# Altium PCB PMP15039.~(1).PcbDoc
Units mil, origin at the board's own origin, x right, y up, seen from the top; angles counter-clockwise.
Board outline 370 x 722 mil, 4 copper layers (Top Layer, MidLayer1, MidLayer2, Bottom Layer), stack 59.4 mil thick; 34 components, 13 nets, 67 pads, 48 vias.
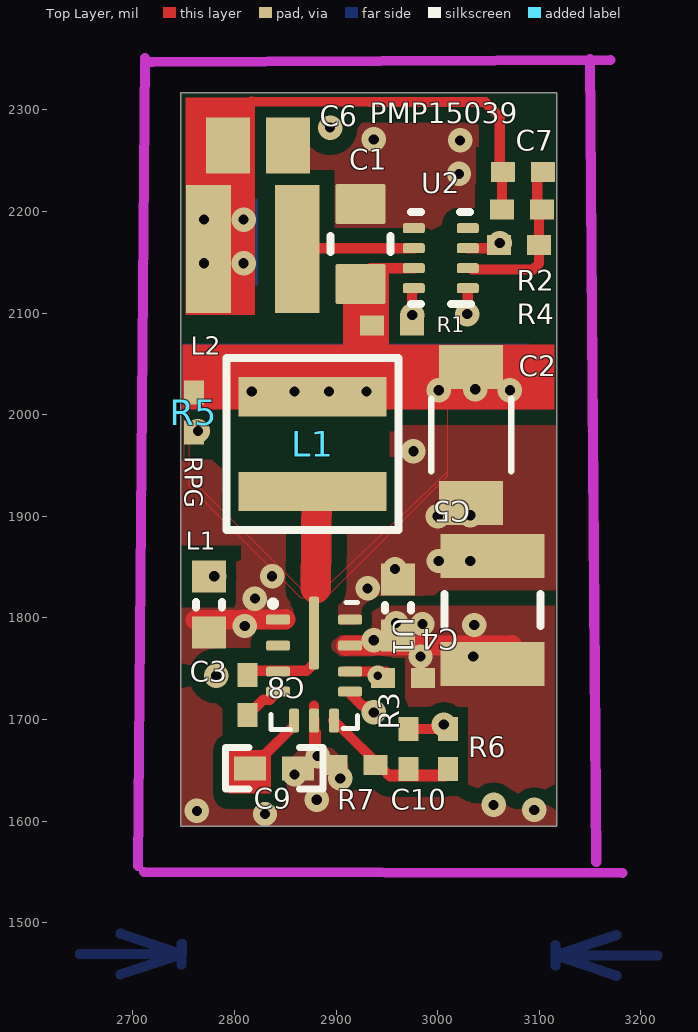
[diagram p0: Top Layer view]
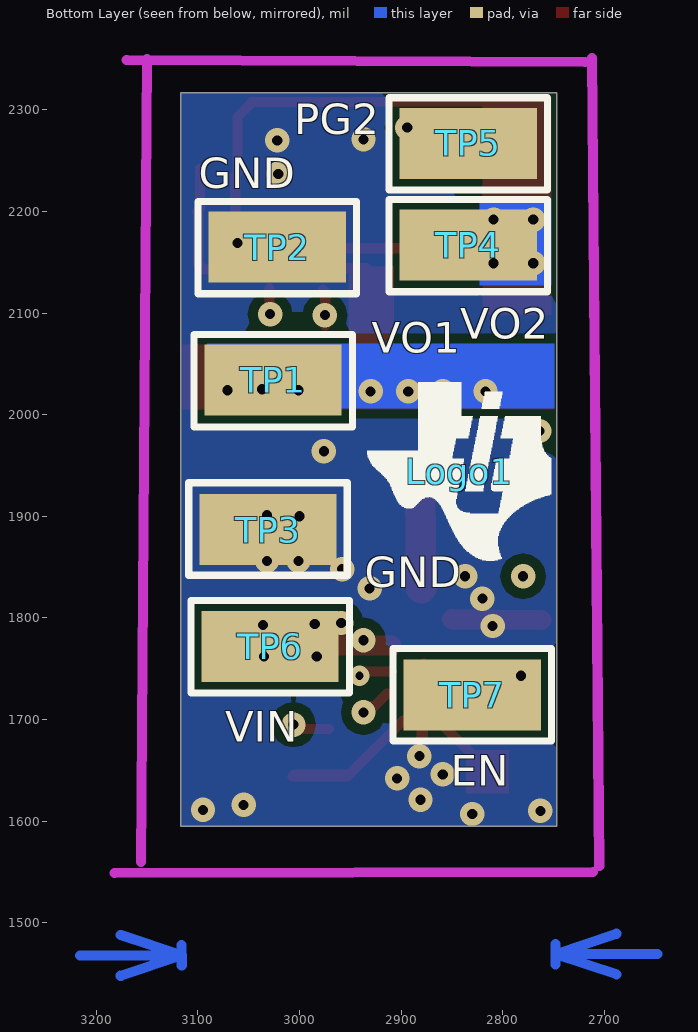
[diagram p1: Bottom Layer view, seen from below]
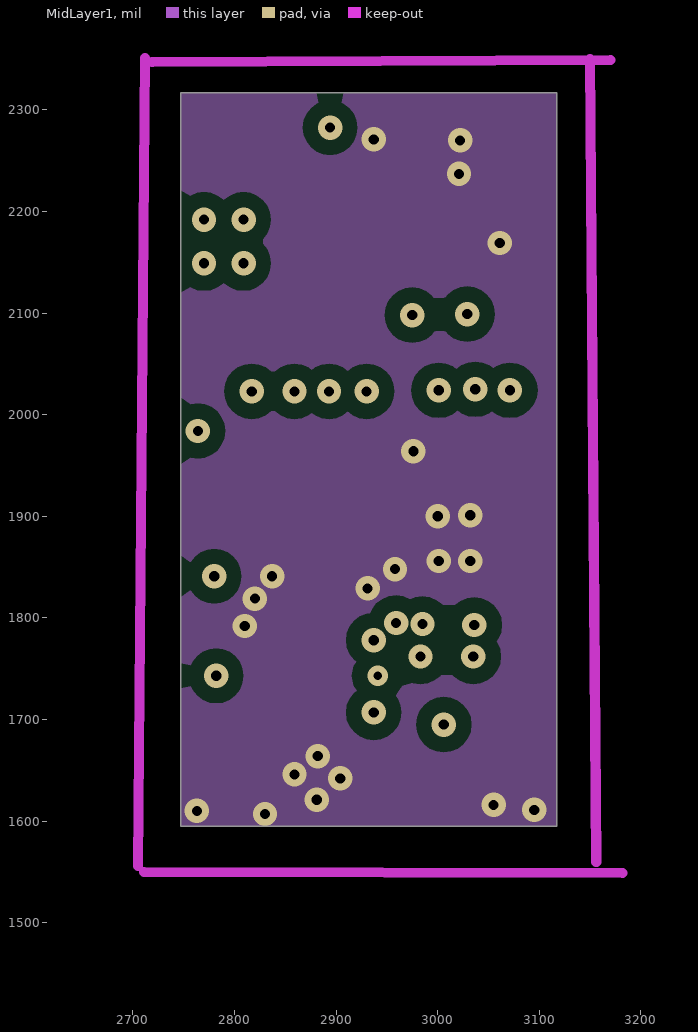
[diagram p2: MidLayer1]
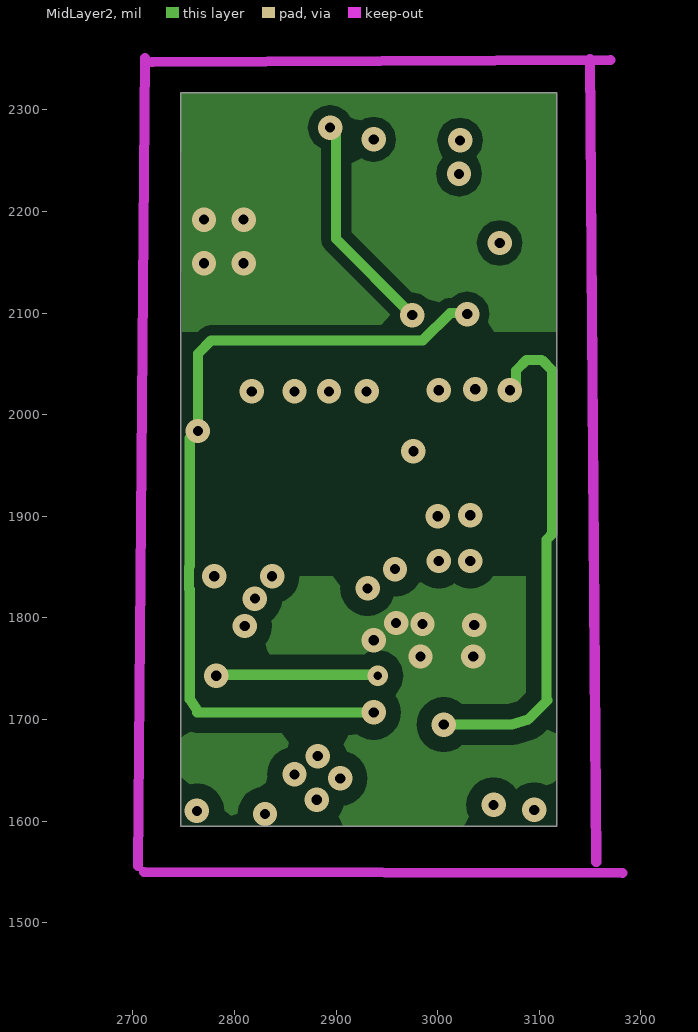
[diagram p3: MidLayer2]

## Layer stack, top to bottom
Top Solder: solder mask 0.4, Solder Resist, Dk 3.5
Top Layer: signal copper 2.8
Dielectric1: core 10, FR-4, Dk 4.8
MidLayer1: signal copper 1.4
Dielectric2: prepreg 31, FR-4, Dk 4.2
MidLayer2: signal copper 1.4
Dielectric3: core 10, FR-4, Dk 4.2
Bottom Layer: signal copper 2.8
Bottom Solder: solder mask 0.4, Solder Resist, Dk 3.5

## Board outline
2747,2317 2747,1595 3117,1595 3117,2317

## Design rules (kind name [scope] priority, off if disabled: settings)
AcuteAngle [All] p1: minimum=4.50000000000000E+0001 checktracksonly=FALSE
AssemblyTestPointUsage [All] p1: valid=2
Clearance Clearance_2 [InNamedPolygon('VIN_L01_P062') Or  InNamedPolygon('Top Layer-No Net 4')] p1: gap=15 ignorepadtopadclearanceinfootprint=FALSE except(0: Arc-Hole Track-Hole SMDPad-Hole THPad-Hole Via-Hole Fill-Hole Poly-Hole Region-Hole Text-Hole)
Clearance Clearance_1 [HasFootprint('Net-Tie_20milWide_60milLong')] p2: gap=10 ignorepadtopadclearanceinfootprint=FALSE except(0: Arc-Hole Track-Hole SMDPad-Hole THPad-Hole Via-Hole Fill-Hole Poly-Hole Region-Hole Text-Hole)
Clearance Clearance_BoardEdge_MountingHoles [OnCopper and InComponentClass('Mounting Holes') vs IsKeepOut] p3: gap=40 ignorepadtopadclearanceinfootprint=FALSE except(0: Arc-Hole Track-Hole SMDPad-Hole THPad-Hole Via-Hole Fill-Hole Poly-Hole Region-Hole Text-Hole)
Clearance Clearance_BoardEdge_Poly [OnCopper and InPoly vs IsKeepOut] p4: gap=25 ignorepadtopadclearanceinfootprint=FALSE except(0: Arc-Hole Track-Hole SMDPad-Hole THPad-Hole Via-Hole Fill-Hole Poly-Hole Region-Hole Text-Hole)
Clearance Clearance_BoardEdge [OnCopper and Not InComponentClass('Logo') and not InComponentClass('FiducialMark') and not InRegion(1000,500,4000,800) and Not IsKeepout vs IsKeepOut] p5: gap=10 ignorepadtopadclearanceinfootprint=FALSE except(0: Arc-Hole Track-Hole SMDPad-Hole THPad-Hole Via-Hole Fill-Hole Poly-Hole Region-Hole Text-Hole)
Clearance Clearance_Poly [InPolygon] p6: gap=10 ignorepadtopadclearanceinfootprint=FALSE except(0: Arc-Hole Track-Hole SMDPad-Hole THPad-Hole Via-Hole Fill-Hole Poly-Hole Region-Hole Text-Hole)
Clearance [All] p7: gap=7.87 ignorepadtopadclearanceinfootprint=FALSE except(0: Arc-Hole Track-Hole SMDPad-Hole THPad-Hole Via-Hole Fill-Hole Poly-Hole Region-Hole Text-Hole)
ComponentClearance [HasFootprint('Net-Tie_20milWide_60milLong')] p1: gap=0 collisioncheckmode=3 verticalgap=0 showdistances=FALSE
ComponentClearance ComponentClearance_1 [All] p2: gap=10 collisioncheckmode=3 verticalgap=10 showdistances=FALSE
ComponentClearance ComponentClearance_Shunt [InComponentClass('Header') vs InComponentClass('Shunt')] p3: gap=0 collisioncheckmode=3 verticalgap=0 showdistances=FALSE
ComponentClearance ComponentClearance_MountingHoles_FiducialMarks [InComponentClass('Mounting Holes') vs InComponentClass('FiducialMark')] p4: gap=50 collisioncheckmode=3 verticalgap=10 showdistances=FALSE
ComponentClearance ComponentClearance_Logo [InComponentClass('Logo')] p5: gap=50 collisioncheckmode=3 verticalgap=10 showdistances=FALSE
ComponentClearance ComponentClearance_ScrewToNut [(HasFootprint('NY PMS 440 0025 PH')) vs (HasFootprint('Keystone_1902C'))] p6: gap=5 collisioncheckmode=3 verticalgap=10 showdistances=FALSE
ComponentClearance ComponentClearance_MountingHoles [InComponentClass('Mounting Holes')] p7: gap=250 collisioncheckmode=3 verticalgap=100000 showdistances=FALSE
ComponentClearance ComponentClearance_SmallPassives [HasFootprint('0201*') or HasFootprint('0402*') or HasFootprint('0508') or HasFootprint('0603*') or HasFootprint('0612') or HasFootprint('0805*') or HasFootprint('0815*') or HasFootprint('0830*') or HasFootprint('1206*') or HasFootprint('1210*') or HasFootprint('1808*') or HasFootprint('1812*') or HasFootprint('1825*') or HasFootprint('2010*') or HasFootprint('2220*') or HasFootprint('2225*') or HasFootprint('2512*') or HasFootprint('2728*') or HasFootprint('3518*') vs HasFootprint('0201*') or HasFootprint('0402*') or HasFootprint('0508') or HasFootprint('0603*') or HasFootprint('0612') or HasFootprint('0805*') or HasFootprint('0815*') or HasFootprint('0830*') or HasFootprint('1206*') or HasFootprint('1210*') or HasFootprint('1808*') or HasFootprint('1812*') or HasFootprint('1825*') or HasFootprint('2010*') or HasFootprint('2220*') or HasFootprint('2225*') or HasFootprint('2512*') or HasFootprint('2728*') or HasFootprint('3518*')] p8: gap=20 collisioncheckmode=3 verticalgap=10 showdistances=FALSE
ComponentClearance ComponentClearance_THtoSMT [IsThruComponent vs IsSMTComponent] p9: gap=40 collisioncheckmode=3 verticalgap=30 showdistances=FALSE
ComponentClearance ComponentClearance_THtoTH [IsThruComponent vs IsThruComponent] p10: gap=118.11 collisioncheckmode=3 verticalgap=30 showdistances=FALSE
DiffPairsRouting [All] p1: maxlimit=100 minlimit=10 mostfreqgap=10 toplayer_minwidth=15 toplayer_maxwidth=15 toplayer_prefwidth=15 midlayer1_minwidth=15 midlayer1_maxwidth=15 midlayer1_prefwidth=15 midlayer2_minwidth=15 midlayer2_maxwidth=15 midlayer2_prefwidth=15 bottomlayer_minwidth=15 bottomlayer_maxwidth=15 bottomlayer_prefwidth=15 maxuncoupledlength=1000
FabricationTestPointUsage TestPointUsage [All] p1: valid=2 allowmultiple=FALSE
FabricationTestpoint Testpoint [All] p1: side=3 testpointundercomponent=TRUE minsize=40 maxsize=100 preferedsize=60 minholesize=0 maxholesize=40 preferedholesize=32 testpointgrid=1 allowsidetop=TRUE allowsidebottom=TRUE usegrid=TRUE gridtolerance=0.01
FanoutControl Fanout_LCC [IsLCC] p1: bgadir=Out bgaviamode=Centered fanoutstyle=Auto fanoutdirection=Alternating viagrid=1 // Fanout_LCC (Default Rule)
FanoutControl Fanout_BGA [IsBGA] p2: bgadir=Out bgaviamode=Centered fanoutstyle=Auto fanoutdirection=Alternating viagrid=1 // Fanout_BGA (Default Rule)
FanoutControl Fanout_Default [All] p4: bgadir=Out bgaviamode=Centered fanoutstyle=Auto fanoutdirection=Alternating viagrid=1 // Fanout_Default (Default Rule)
FanoutControl Fanout_Small [(CompPinCount < 5)] p5: bgadir=Out bgaviamode=Centered fanoutstyle=Auto fanoutdirection=OutThenIn viagrid=1 // Fanout_Small (Default Rule)
HoleSize [All] p1: absolutevalues=TRUE maxlimit=251 minlimit=8 maxpercent=80.000 minpercent=20.000
MinimumAnnularRing MinimumAnnularRing_ThermalPadVias [IsVia and InAnyComponent] p1: minimumring=5.91
MinimumAnnularRing [All] p2: minimumring=7
MinimumSolderMaskSliver MinimumSolderMaskSliver_Logo [InComponentClass('Logo') vs InComponentClass('Logo')] p1 off: minsoldermaskwidth=0.7
MinimumSolderMaskSliver [All] p2 off: minsoldermaskwidth=3.94
PlaneClearance [All] p1: clearance=10
PlaneConnect [All] p1: planeconnectstyle=Direct reliefexpansion=10 reliefentries=4 reliefconductorwidth=10 reliefairgap=10
PolygonConnect [All] p1: connectstyle=Direct reliefconductorwidth=10 reliefentries=4 polygonreliefangle="90 Angle" airgapwidth=10
RoutingVias ThermalPadVias [IsVia and InAnyComponent] p1: holewidth=7.87 width=19.68 viastyle="Through Hole" minholewidth=7.87 minwidth=19.68 maxholewidth=12.99 maxwidth=23.62
RoutingVias [All] p2: holewidth=16 width=34 viastyle="Through Hole" minholewidth=7.87 minwidth=24 maxholewidth=40 maxwidth=65
SMDToCorner [All] p1: distance=30000
SilkToSilkClearance [All] p1: silktosilkclearance=5
SilkToSolderMaskClearance SilkscreenOverComponentPads [IsPad] p1: minsilkscreentomaskgap=5 clearancetoexposedcopper=TRUE
SolderMaskExpansion [All] p1: expansion=1.97
Width [All] p1: maxlimit=5000 minlimit=8 preferedwidth=10 checkconnectedcopper=TRUE
15 further rules are at their usual default settings.

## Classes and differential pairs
component class PMP15039_Hardware: !PCB1 Logo1 ZZ1 ZZ2 ZZ3 ZZ4 ZZ5
component class AssemblyNote: ZZ1 ZZ2 ZZ3 ZZ4
component class Logo: Logo1

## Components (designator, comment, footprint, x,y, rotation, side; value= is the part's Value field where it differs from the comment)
C1 "JMK107BB7475MA-T" 0805_HV1 2924,2168 r90 top value=4.7uF
C2 "GRM21BZ71A226ME15L" 1206_190 3033,1980 r270 top value=22uF
C3 "CIN3" 0603L 2775,1813 r270 top value=0.047uF
C4 "CIN1" 0603L 2961,1810 r90 top value=0.047uF
C5 "CIN2" 1210_220L 3054,1808 r270 top value=4.7uF
C6 "GRM21BR71A106ME51L" 0805L 2823,2265 r0 top value=10uF
C7 "GRM1555C1H121FA01D" 0402L 3084,2239 r0 top value=120pF
C8 "CB" 0402L 2813,1724 r90 top value=0.1uF
C9 "C1005X7S1A105K050BC" 0402 2839,1652 r0 top value=1uF
C10 "CFF" 0402L 2971,1671 r270 top value=20pF
L1 "74438357100" WE-MAPI_4030 2877,1971 r90 top value=10uH
L2 "XFL3012-152MEB" XFL3012 2818,2163 r180 top value=1.5uH
Logo1 "Texas Instruments" TI_Symbol_Overlay_Small 2843,1944 r180 bottom
R1 "RPG2" 0402L 2955,2088 r180 top value=10.0k
R2 "RFBT2" 0402L 3083,2202 r180 top value=150k
R3 "CRCW0402100KFKED" 0402L 2966,1741 r180 top value=100k
R4 "RFBB2" 0402L 3080,2167 r0 top value=100k
R5 "RPG" 0402L 2760,2002 r90 top value=100k
R6 "CRCW0402100KFKED" 0402L 3010,1671 r90 top value=100k
R7 "CRCW040224K9FKED" 0402L 2919,1655 r0 top value=24.9k
TP1 "VO1" Testpoint_Keystone_Miniature 3026,2034 r180 bottom
TP2 "GND" Testpoint_Keystone_Miniature 3022,2165 r180 bottom
TP3 "GND" Testpoint_Keystone_Miniature 3031,1887 r0 bottom
TP4 "VO2" Testpoint_Keystone_Miniature 2834,2167 r180 bottom
TP5 "PG2" Testpoint_Keystone_Miniature 2834,2267 r180 bottom
TP6 "VIN" Testpoint_Keystone_Miniature 3029,1772 r180 bottom
TP7 "EN" Testpoint_Keystone_Miniature 2830,1724 r0 bottom
U1 "LMR36006BRNXR" RNX0012B 2878.3,1754 r0 top
U2 "TPS62821DLC" DLC0008A 3003,2154 r180 top
ZZ1 "This Assembly Note is for PCB labels only" AssemblyNoteLabel 5490,1926 r90 top
ZZ2 "This Assembly Note will show in the PcbDoc and associated outputs" AssemblyNote 5803,2338 r90 top
ZZ3 "This Assembly Note will show in the PcbDoc and associated outputs" AssemblyNote 6826,1666 r90 top
ZZ4 "This Assembly Note will show in the PcbDoc and associated outputs" AssemblyNote 5340,1979 r90 top
ZZ5 "This Assembly Note will show in the PcbDoc and associated outputs" AssemblyNote 5202,2804 r90 top

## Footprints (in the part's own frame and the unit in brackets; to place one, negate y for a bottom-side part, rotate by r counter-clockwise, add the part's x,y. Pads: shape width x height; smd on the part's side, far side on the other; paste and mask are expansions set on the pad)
0402 [mm] "0402 from SM-752 data"
  rect 0.8x0.6 smd: 1(-0.6,0) 2(0.6,0)
  silkscreen extent -1.22,-0.52 1.22,0.52, body extent -0.55,-0.3 0.55,0.3, height 0.6
0402L [mm] "0402 from SM-752 data"
  rect 0.6x0.5 smd: 1(-0.5,0) 2(0.5,0)
  body extent -0.55,-0.3 0.55,0.3, height 0.6
0603L [mm] "0603 from SM-752 data"
  rect 0.8x0.85 smd: 1(-0.7,0) 2(0.7,0)
  silkscreen extent -0.07,-0.33 0.07,0.33, body extent -0.87,-0.47 0.87,0.47, height 1
0805_HV1 [mm] "Custom footprint based on analyzing multiple manufacturer recommendations"
  rrect10% 1x1.25 smd: 1(-1,0) 2(1,0)
  silkscreen extent -0.2,-0.75 0.2,0.75, body extent -1.1,-0.72 1.1,0.73, height 1.45
0805L [mm] "0805 from SM-752 data"
  rect 1.1x1.4 smd: 1(-0.75,0) 2(0.75,0)
  body extent -1.1,-0.72 1.1,0.72, height 1.45
1206_190 [mm] "1206_190"
  rect 1.1x1.6 smd: 1(-1.7,0) 2(1.7,0)
  silkscreen extent -0.9,-1 0.9,1, body extent -1.75,-0.95 1.75,0.95, height 1.9
1210_220L [mm] "1210"
  rect 1.1x2.6 smd: 1(-1.35,0) 2(1.35,0)
  silkscreen extent -0.4,-1.2 0.4,1.2, body extent -1.7,-1.35 1.7,1.35, height 2.2
AssemblyNote [mil] "Assembly Note"
AssemblyNoteLabel [mil] "Assembly Note for PCB Labels"
DLC0008A [mm] "QFN-8 (2.0mmX1.5mm)"
  rrect40% 0.55x0.25 smd: 1(-0.675,0.75) 2(-0.675,0.25) 3(-0.675,-0.25) 4(-0.675,-0.75) 5(0.675,-0.75) 6(0.675,-0.25) 7(0.675,0.25) 8(0.675,0.75)
  silkscreen extent -0.75,-1.15 0.75,1.15, body extent -0.8,-1.05 0.8,1.05, height 1.02
RNX0012B [mm] "VQFN-HR-12"
  rrect40% 0.6x0.25 smd: 1(-0.9,1.125) 2(-0.9,0.475) 3(-0.9,-0.175) 4(-0.9,-0.675) 8(0.9,-0.675) 9(0.9,-0.175) 10(0.9,0.475) 11(0.9,1.125)
  rrect40% 0.25x0.6 smd: 5(-0.5,-1.4) 6(0,-1.4) 7(0.5,-1.4)
  rrect40% 0.25x0.812 on Top Paste: 12(0,0.28) 12(0,1.295)
  rrect40% 0.25x1.825 smd paste-0.175: 12(0,0.788)
  body extent -1,-1.5 1,1.5, height 1
Testpoint_Keystone_Miniature [mil] "Miniature SMT test point"
  rect 135x70 smd: 1(0,0)
  silkscreen extent -78,-46 78,45, body extent -52,-20 52,20, height 61
TI_Symbol_Overlay_Small [mil]
  silkscreen extent -90,-88 91,88
WE-MAPI_4030 [mm] "SMD, 2-Leads, Body 4.1x4.1mm"
  rect 0.98x3.7 smd: 1(-1.185,0) 2(1.185,0)
  silkscreen extent -2.15,-2.15 2.15,2.15, body extent -2.05,-2.05 2.05,2.05, height 3.1
XFL3012 [mm] "Coilcraft"
  rect 1.12x3.2 smd: 1(-1.11,0) 2(1.11,0)
  body extent -1.6,-1.6 1.6,1.6, height 1.3

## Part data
C1: library part CMP-0007503-4, "CAP, CERM, 4.7 uF, 6.3 V, +/- 10%, X7R, 0603", Cap_Case=0603, Manufacturer="Taiyo Yuden", TempCo=X7R, Tolerance_%=10%, Value1=Unknown, Value2=6.3V, ValueDisplayed=4.7uF
C2: library part CMP-0008377-2, "CAP, CERM, 22 uF, 10 V, +/- 20%, X7R, 0805", Cap_Case=0805, Manufacturer=MuRata, Supplier Part Number 1=81-GRM21BZ71A226ME5L, TempCo=X7R, Tolerance_%=20%, Value1=Unknown, Value2=10V, ValueDisplayed=22uF
C3 C4: library part CGA3E3X7S2A473K080AB, "CAP, CERM, 0.047 µF, 100 V,+/- 10%, X7S, AEC-Q200 Grade 1, 0603", Cap_Case=0603, Manufacturer=TDK, Supplier Part Number 1=445-6936-1-ND, TempCo=X7S, Tolerance_%=10, Value1="0.089796 ohm", Value2=100V, ValueDisplayed=0.047µF
C5: library part CGA6M3X7S2A475K200AB, "CAP, CERM, 4.7 µF, 100 V, +/- 10%, X7S, AEC-Q200 Grade 1, 1210", Cap_Case=1210_220, Manufacturer=TDK, Supplier Part Number 1=445-7005-1-ND, TempCo=X7S, Tolerance_%=10, Value1="0.004236 ohm", Value2=100V, ValueDisplayed=4.7µF
C6: library part CMP-0008316-2, "CAP, CERM, 10 uF, 10 V, +/- 20%, X7R, 0805", Cap_Case=0805, Manufacturer=MuRata, Supplier Part Number 1=490-8316-1-ND, TempCo=X7R, Tolerance_%=20%, Value1=Unknown, Value2=10V, ValueDisplayed=10uF
C7: library part CMP-0006416-2, "CAP, CERM, 120 pF, 50 V, +/- 1%, C0G/NP0, 0402", Cap_Case=0402, Manufacturer=MuRata, Supplier Part Number 1=490-8182-1-ND, TempCo=C0G/NP0, Tolerance_%=1%, Value1=Unknown, Value2=50V, ValueDisplayed=120pF
C8: library part CMP-0006659-2, "CAP, CERM, 0.1 uF, 25 V, +/- 10%, X7R, 0402", Cap_Case=0402, Manufacturer=MuRata, PartNumber=GRM155R71E104KE14D, Supplier Part Number 1=490-10698-1-ND, TempCo=X7R, Tolerance_%=10%, Value1=Unknown, Value2=25V, ValueDisplayed=0.1uF
C9: library part CMP-0006300-2, "CAP, CERM, 1 uF, 10 V, +/- 10%, X7S, 0402", Cap_Case=0402, Manufacturer=TDK, Supplier Part Number 1=445-9116-1-ND, TempCo=X7S, Tolerance_%=10%, Value1="0.011416 ohm", Value2=10V, ValueDisplayed=1uF
C10: library part GRM1555C1E200JA01D, "CAP, CERM, 20 pF, 25 V,+/- 5%, C0G/NP0, 0402", Cap_Case=0402, Manufacturer=MuRata, Supplier Part Number 1=490-11364-1-ND, TempCo=C0G/NP0, Tolerance_%=5, Value2=25V, ValueDisplayed=20pF
L1: library part CMP-0081728-1, "Inductor, Shielded, Metal Composite, 10 µH, 2.7 A, 0.11 ohm, SMD", Manufacturer="Wurth Elektronik", Supplier Part Number 1=732-11206-1-ND, Value1="0.11 ohm", Value2=2.7A, ValueDisplayed=10µH
L2: library part CMP-0061135-1, "Inductor, Shielded, Composite, 1.5 uH, 2.2 A, 0.06 ohm, SMD", Manufacturer=Coilcraft, Value1="0.06 ohm", Value2=2.2A, ValueDisplayed=1.5uH
Logo1: library part TI_Logo, "Texas Instrument Corporate Signature"
R1: library part CMP-0025958-2, "RES, 10.0 k, 1%, 0.063 W, 0402", Manufacturer=Vishay-Dale, PartNumber=CRCW040210K0FKED, Power_W=63mW, Supplier Part Number 1=541-10.0KLCT-ND, TempCo="100 ppm/C", Tolerance_%=1%, Value2=0.063W, Value_Code=10k0, ValueDisplayed=10.0k
R2: library part CMP-0026669-1, "RES, 150 k, 1%, 0.1 W, AEC-Q200 Grade 0, 0402", Manufacturer=Panasonic, PartNumber=ERJ-2RKF1503X, Power_W=100mW, Supplier Part Number 1=P150KLCT-ND, TempCo="100 ppm/C", Tolerance_%=1%, Value2=0.1W, Value_Code=150k
R3 R6: "RES, 100 k, 1%, 0.063 W, 0402", Manufacturer=Vishay-Dale, Power_W=0.063, Supplier Part Number 1=541-100KLCT-ND, TempCo="100 ppm/C", Tolerance_%=1, Value1=1%, Value2=0.063W, Value_Code=100k
R4: library part CMP-0025950-2, "RES, 100 k, 1%, 0.063 W, 0402", Manufacturer=Vishay-Dale, PartNumber=CRCW0402100KFKED, Power_W=63mW, Supplier Part Number 1=541-100KLCT-ND, TempCo="100 ppm/C", Tolerance_%=1%, Value2=0.063W, Value_Code=100k
R5: library part CRCW0402100KFKED, "RES, 100 k, 1%, 0.063 W, 0402", Manufacturer=Vishay-Dale, Power_W=0.063, Supplier Part Number 1=541-100KLCT-ND, TempCo="100 ppm/C", Tolerance_%=1, Value1=1%, Value2=0.063W, Value_Code=100k
R7: library part CMP-0026196-1, "RES, 24.9 k, 1%, 0.063 W, 0402", Manufacturer=Vishay-Dale, Power_W=63mW, Supplier Part Number 1=541-24.9KLCT-ND, TempCo="100 ppm/C", Tolerance_%=1%, Value2=0.063W, Value_Code=24k9, ValueDisplayed=24.9k
TP1 TP2 TP3 TP4 TP5 TP6 TP7: library part CMP-0055152-1, "Test Point, Miniature, SMT", Manufacturer=Keystone, PartNumber=5015, Supplier Part Number 1=36-5015TR-ND
U1: library part CMP-0077274-3, "65-V 0.6-A Synchronous Step-Down Converter, RNX0012B (VQFN-HR-12)", Alternate Manufacturer="Texas Instruments", Alternate PartNumber=LMR36006BRNXT
U2: library part CMP-0065148-2, "2.5-V to 5.5-V, 1-, 2-, 3-A Step-Down Converter with DCS-Control, DLC0008A (SON-HR-8)", Alternate Manufacturer="Texas Instruments"
ZZ1: library part AssemblyNoteLabel
ZZ2 ZZ3 ZZ4: library part AssemblyNote
ZZ5: library part "Assembly Note"

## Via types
v1: diameter 24, hole 10, Top Layer to Bottom Layer, tented both sides, 46 vias
v2: diameter 20, hole 8, Top Layer to Bottom Layer, tented both sides, 1 vias
v3: diameter 24/24/24/24 (per signal layer), hole 10, Top Layer to Bottom Layer, tented both sides, 1 vias

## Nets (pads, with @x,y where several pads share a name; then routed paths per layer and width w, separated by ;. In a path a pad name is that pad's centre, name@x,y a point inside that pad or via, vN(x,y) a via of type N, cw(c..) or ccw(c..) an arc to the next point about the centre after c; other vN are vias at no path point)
EN: R3.2 TP7.1 U1.9 | length 186.2
  Top Layer w10: U1.9@2909.8,1747.11 R3.2@2949,1747
  MidLayer2 w10: v1@2790,1744 v2@2937,1744
  other v1: 2782,1743
  other v2: 2941,1743
FB: C10.2 R6.1 R7.2 U1.7 | length 190.1
  Top Layer w10: U1.7@2897,1699 2898,1699 2951,1646 ; 2950.56,1646 2951,1646 ; 2951,1646 3002.44,1646 3005,1646 3007,1644 3001,1644 2953,1644 2951,1646
GND: C1.2 C2.2 C3.2 C4.2 C5.1 C6.2 C9.2 R4.1 R7.1 TP2.1 TP3.1 U1.1 U1.6 U1.11 U2.3 U2.5 | length 181.1
  Top Layer w10: 2878.3,1713.69 2878.3,1702.82 2878.3,1700.19 2878.55,1699.94 2878.55,1669.45 v1@2882.11,1673 ; v1@2880,1672.31 2880,1687 ; U2.3 3056.16,2163.84 R4.1@3058,2162
  Top Layer w20: C3.2@2762,1798 U1.1@2849.8,1798.7
  other v1: 2830,1607 2763,1610 3095,1611 3055,1616 2881,1621 2904,1642 2859,1646 2882,1664 2810,1792 2820,1819 2837,1841 2958,1848 3001,1856 3032,1856 3000,1900 3032,1901 2976,1964 3061,2169 3021,2237 3022,2270 2937,2271
  other v3: 2931,1829
NetC7_2: C7.2 R2.1 R4.2 U2.2 | length 163.1
  Top Layer w10: U2.2@3034,2143 3094,2143 3099.69,2148.69 R4.2 3099.69,2198.69 3101,2200 3098,2203 C7.2@3098,2242
NetC8_1: C8.1 U1.4 | length 40.3
  Top Layer w10: C8.1 2827.69,1719 2828.18,1719 2828.68,1719.5 2834.95,1719.5 U1.4 U1.4@2842.29,1728
NetC8_2: C8.2 L1.1 U1.3 U1.12@2878.3,1785.02 | length 164.7
  Top Layer w10: C8.2 2817.31,1748 2871,1748 U1.12@2878,1755
  Top Layer w30: 2880,1829 L1.1@2881,1924
NetL2_1: L2.1 U2.6 | length 110.8
  Top Layer w10: L2.1@2866,2163 2866.84,2163.84 U2.6
NetR1_1: R1.1 TP5.1 U2.8 | length 265.3
  Top Layer w10: R1.1 2974.69,2120.68 U2.8@2977,2123
  MidLayer2 w10: v1@2892,2287 2900,2287 2900,2173 v1(2975,2098) v1@2975.87,2097.13
  other v1: 2894.06,2282.61
PGOOD: R5.1 U1.8 U2.1 | length 863.6
  Top Layer w10: U1.8@2913.95,1725.45 2926.3,1713.1 v1@2931.9,1713.1 ; v1@3029.57,2099 U2.1
  MidLayer2 w10: 2763,1707 v1@2932,1707 ; 2763,1710 2756,1720 2756,1827.82 2755.13,1828.7 2755.13,1850.18 2756,1851.05 2756,1977 v1@2763.5,1984.5 ; v1(2764,1984) 2764,2060 2777.13,2073.13 2985.3,2073.13 3012.18,2100 3033,2100 v1@3033,2099 ; v1@3030,2096 v1@3030,2099
  other v1: 2937,1707 3029,2099
VCC: C9.1 U1.5 | length 78.5
  Top Layer w10: C9.1@2809,1645 2854.8,1690.17 2858.61,1694.32 U1.5@2858.61,1702.82
VIN: C3.1 C4.1 C5.2 R3.1 TP6.1 U1.2 U1.10 | length 163.2
  Top Layer w20: U1.10@2909.8,1772.7 C5.2@3073,1773
  other v1: 2983,1762 3035,1762 2937,1778 3036,1793 2985,1794 2959,1795 2780,1841
VO1: C1.1 C2.1 C10.1 L1.2 R1.2 R5.2 R6.2 TP1.1 U2.7 | length 583.5
  Top Layer w10: C1.1@2934,2144 2934.16,2144.16 U2.7 ; C10.1 3008.69,1690.68 R6.2@3011,1693
  MidLayer2 w10: v1(3006,1695) 3073,1695 3089,1700 3108,1719 ; v1@3077,2031 3077,2043.53 3087.47,2054 3102.28,2054 3112.75,2043.53 3112.75,1882.75 3107,1877 3107,1719
  Bottom Layer w10: TP1.1@3085.87,2040.87 TP1.1@3086,2041
  Bottom Layer w30: TP1.1@3053,2035 TP1.1@3055,2030
  other v1: 2817,2023 2859,2023 2893,2023 2930,2023 3001,2024 3071,2024 3037,2025
VO2: C6.1 C7.1 L2.2 R2.2 TP4.1 | length 341.8
  Top Layer w10: 2816.95,2308.31 3047,2307.5 ; 3047,2307 3061,2293 3061,2238 3063.31,2235.69 R2.2
  other v1: 2770,2149 2809,2149 2770,2192 2809,2192
pads on no net: U1.12@2878.3,1765.02 U1.12@2878.3,1804.98 U2.4
copper on no net: | length 493
  Bottom Layer w10: 2648,1469.27 2748,1469 ; 2687.95,1449.16 2748,1469 ; 2688.05,1489.16 2748,1469 ; 2747.97,1459 2748.03,1479 ; 3115.97,1458 3116.03,1478 ; 3175.95,1447.84 3116,1468 ; 3176.05,1487.84 3116,1468 ; 3216,1467.73 3116,1468

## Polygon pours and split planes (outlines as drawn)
GND on Top Layer "Top Layer-No Net 4" (solid, remove dead copper, pour order 19): 3117,1595 2747,1595 2747,2400 3117,2400
GND on Top Layer "GND_L01_P044" (solid, remove dead copper, pour order 44): 2855,1793 2812,1793 2762,1843 2747,1843 2747,1924 2855,1816
GND on Top Layer "GND_L01_P046" (solid, remove dead copper, pour order 46): 2902,1792.49 2902,1812 3030,1940 3115,1940 3115,1843 3018,1843 2968.52,1793.52
VIN on Top Layer "VIN_L01_P018" (solid, remove dead copper, pour order 18): 2747,1812 2747,1608 3115,1608 3115,1812
NetC8_1 on Top Layer "NETC8_1_L01_P048" (solid, remove dead copper, pour order 48): 2887.89,1828 3010,1944 3010,2020 2750,2020 2750,1950 2750,1944 2866,1828
NetC8_1 on Top Layer "NETC8_1_L01_P050" (solid, remove dead copper, pour order 50): 2890,1820 3010,1940 3010,1950 3010,2025 2755,2025 2755,1930 2865,1820
VIN on Top Layer "VIN_L01_P052" (solid, remove dead copper, pour order 52): 3015,1820 3115,1820 3115,1755 3015,1755
GND on Bottom Layer "GND_L04_P030" (solid, remove dead copper, pour order 30): 3117,1595 2747,1595 2747,2317 3117,2317
VIN on MidLayer2 "Top Layer-No Net 4" (solid, pour order 20): 3117,1595 2747,1595 2747,1841 3117,1841
VO2 on MidLayer2 "VO2_L03_P072" (solid, remove dead copper, pour order 72): 2747.52,2317 3117,2317 3117,2081.54 2748.44,2081.54
GND on MidLayer1 "Top Layer-No Net 4" (solid, pour order 17): 3117,1595 2747,1595 2747,2317 3117,2317

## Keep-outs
Keep-Out Layer:
  lines w10: 2705,1556 2712,2351 ; 2711,1550 3182,1549 ; 2719,2347 3170,2349 ; 3150,2350 3156,1560
  text ".Layer_Name" at -1136,-1239.49 h60

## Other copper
Top Layer:
  region net VO2: 2752,2312 2752,2098 2820,2098 2820,2312
  rectangle net VCC: 2794,1627 2836,1670
  rectangle net VO1: 2749,2005 3115,2069
  rectangle net VO1: 2907,2040 2952,2146
  pour cut-out: 2788,2003 2790,2001 2953,2001 2953,1900 2952,1899 2787,1899
  text ".Layer_Name" at -1136,-1239.49 h60
Bottom Layer:
  region net VO2: 2752,2213 2752,2127 2823,2127 2823,2213
  rectangle net VO1: 2749,2006 3091,2070
  text "368.001 (mil)" at 2580.72,1325.49 h60 r359.84
  text ".Layer_Name" at -1136,-1239.49 h60

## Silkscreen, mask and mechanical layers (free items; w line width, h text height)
Top Overlay:
  circle w10: c2838,1814 r1
  lines w5: 2836,1690 2855,1690 ; 2836,1692 2836,1705 ; 2907,1691 2921,1691 ; 2910,1815 2921,1815 ; 2921,1692 2921,1704
  text "PMP15039" at 2933,2287 h20
  text "L1" at 2752,1867 h18
  text ".Layer_Name" at -1136,-1239.49 h60
Bottom Overlay:
  text ".Layer_Name" at -1136,-1239.49 h60
Top Paste:
  text ".Layer_Name" at -1136,-1239.49 h60
Bottom Paste:
  text ".Layer_Name" at -1136,-1239.49 h60
Top Solder:
  text ".Layer_Name" at -1136,-1239.49 h60
  text ".Layer_Name" at -1136,-1239.49 h60
Bottom Solder:
  text ".Layer_Name" at -1136,-1239.49 h60
Drill Guide:
  text ".Layer_Name" at -1136,-1239.49 h60
M1 Board Outline:
  lines w47.24: 2722,2345 2721.02,1574.49 3149.21,1571.65 3148.21,2346.05 2728,2347
  text ".Layer_Name" at -1136,-1239.49 h60
M2 Board Dimensions:
  rectangle: -1713,-666.5 -1588,-541.5
  rectangle: -1588,-791.5 -1213,-666.5
  lines w7: -1713,-666.5 -713,-666.5 ; -1588,-791.5 -1588,-541.5 ; -1463,-791.5 -1463,-541.5 ; -1213,-791.5 -1213,-541.5 ; -963,-791.5 -963,-541.5 ; -1713,-791.5 -713,-791.5 -713,-541.5 -1713,-541.5 -1713,-791.5
  text ".Layer_Name" at -1136,-1239.49 h60
M3 3D STEP Top:
  text ".Layer_Name" at -1136,-1239.49 h60
M4 3D STEP Bottom:
  text ".Layer_Name" at -1136,-1239.49 h60
M5 Assembly Top:
  lines w10: -2005,-1311.17 4595,-1311.17 ; -2005,-1107.83 4597,-1107.83 ; -2005,-904.5 -2005,-1514.5 2000,-1514.5 4597,-1514.5 4597,-904.5 -2004.5,-904.5 -2004.5,-1514.5 -429,-1514.5 ; 460,-1514.5 460,-904.5 ; 1727,-1107.83 1727,-904.5 ; 2567,-1107.83 2567,-904.5 ; 3189,-1521 3189,-1318.17
  text "COMPONENTS MARKED 'DNP' SHOULD NOT BE POPULATED." at -559.5,-699.5 h60
  text "ASSEMBLY VARIANT:" at -560,-815 h60
  text ".VariantName" at 476,-815 h60
  text "PCB VIEWED FROM TOP SIDE" at -1941.5,-1036.67 h60
  text "BOARD #:" at 535,-1036.67 h60
  text ".PRJ_Number" at 1080.5,-1036.67 h60
  text "REV:" at 1925,-1036.67 h60
  text ".PCB_Rev" at 2216.5,-1036.67 h60
  text "SVN REV:" at 2763,-1036.67 h60
  text ".VersionControl_RevNumber" at 3269,-1036.67 h60
  text "IGNORE ->" at -1941.5,-1239.49 h60
  text "PLOT NAME =" at -1941.5,-1445.34 h60
  text ".plot_File_Name" at -1136,-1445.34 h60
  text "GENERATED    :" at 537,-1445.34 h60
  text ".Print_Date" at 1406.5,-1445.34 h60
  text ".Print_Time" at 2135.5,-1445.34 h60
  text "TEXAS INSTRUMENTS" at 3400,-1445.34 h60
M6 Assembly Bottom:
  lines w10: -2005.5,-1108.33 4596.5,-1108.33 ; -2003.5,-1311.67 4596.5,-1311.67 ; -597.5,-1521.5 -597.5,-1318.67 ; 24.5,-1108.33 24.5,-905 ; 864.5,-1108.33 864.5,-905 ; 2131.5,-1515 2131.5,-905 ; 3020.5,-1515 4596,-1515 4596,-905 -2005.5,-905 -2005.5,-1515 591.5,-1515 4596.5,-1515 4596.5,-905
  text "COMPONENTS MARKED 'DNP' SHOULD NOT BE POPULATED." at 4389,-699 h60
  text ".VariantName" at 3345,-815 h60
  text "ASSEMBLY VARIANT:" at 4384,-815 h60
  text ".VersionControl_RevNumber" at -677.5,-1037.17 h60
  text "SVN REV:" at -171.5,-1037.17 h60
  text ".PCB_Rev" at 375,-1037.17 h60
  text "REV:" at 666.5,-1037.17 h60
  text ".PRJ_Number" at 1511,-1037.17 h60
  text "BOARD #:" at 2056.5,-1037.17 h60
  text "PCB VIEWED FROM BOTTOM SIDE" at 4533,-1037.17 h60
  text "IGNORE ->" at 834.85,-1239.49 h60
  text "TEXAS INSTRUMENTS" at -808.5,-1445.84 h60
  text ".Print_Time" at 456,-1445.84 h60
  text ".Print_Date" at 1185,-1445.84 h60
  text "GENERATED    :" at 2054.5,-1445.84 h60
  text ".plot_File_Name" at 3727.5,-1445.84 h60
  text "PLOT NAME =" at 4533,-1445.84 h60
M9 Title Sheet:
  drawing of 57 lines, arcs and shapes, not listed
  text "1" at -973.16,7655.5 h70
  text "2" at 1522.5,7655.5 h70
  text "3" at 4011.84,7655.5 h70
  text "4" at 6518.51,7655.5 h70
  text "5" at 9017.5,7655.5 h70
  text "A" at -2129.5,6512.5 h70
  text "A" at 12670.5,6512.5 h70
  text "B" at -2129.5,4132.5 h70
  text "B" at 12670.5,4132.5 h70
  text "C" at -2129.5,1757.5 h70
  text "C" at 12670.5,1757.5 h70
  text "PROJECT TITLE:" at 9630.5,-103.5 h45
  text ".PRJ_Title" at 9680.5,-236.83 h70
  text "DESIGNED FOR:" at 9630.5,-404.5 h45
  text ".PRJ_Customer" at 9680.5,-544.5 h70
  text "D" at -2129.5,-612.5 h70
  text "D" at 12670.5,-612.5 h70
  text "FILE NAME:" at 9630.5,-704.5 h45
  text ".PCB_File_Name_No_Path" at 9680.5,-824.5 h70
  text "Texas Instruments (TI) and/or its licensors do not warrant the accuracy or completeness of this specification" at 4661,-986.34 h45
  text "ENGINEER:" at 9630.5,-994.5 h45
  text "LAYOUT BY:" at 11135.5,-994.5 h45
  text "or any information contained therein. TI and/or its licensors do not warrant that this design will meet" at 4616.01,-1099 h45
  text ".PRJ_Engineer" at 9680.5,-1149.49 h70
  text ".PCB_Layout" at 11186,-1149.49 h70
  text "the specifications, will be suitable for your application or fit for any particular purpose, or will operate in" at 4616.01,-1211.67 h45
  text ".Layer_Name" at -1136,-1239.49 h60
  text "ALTIUM DESIGNER VERSION:" at 11135.5,-1304.5 h45
  text "an implementation. TI and/or its licensors do not warrant that the design is production worthy. You should" at 4616.01,-1324.33 h45
  text "completely validate and test your design implementation to confirm the system functionality for your application." at 4661,-1437 h45
  text ".print_Scale" at 9680.5,-1437.83 h70
  text ".Application_BuildNumber" at 11186,-1437.83 h70
  text "1" at -973.16,-1644.5 h70
  text "2" at 1522.5,-1644.5 h70
  text "3" at 4011.84,-1644.5 h70
  text "4" at 6518.51,-1644.5 h70
  text "5" at 9017.5,-1644.5 h70
  text "6" at 11522.5,-1644.5 h70
M10 Fab Notes:
  drawing of 185 lines, arcs and shapes, not listed
  text "DESIGN INFORMATION" at 10668.02,5529 h60
  text "MIN. TRACK WIDTH:" at 10023.46,5349 h60
  text "8" at 11119.7,5349 h60
  text "MIL" at 11274.46,5349 h60
  text "MIN. CLEARANCE:" at 10023.46,5217 h60
  text "0.2" at 11059.7,5217 h60
  text "mm" at 11274.46,5217 h60
  text "MIN. VIA PAD SIZE:" at 10023.46,5085 h60
  text "24" at 11089.71,5085 h60
  text "MIL" at 11274.46,5085 h60
  text "0.05mm (2MIL)" at 10718.46,4943.29 h60
  text "MINIMUM ANNULAR RING" at 9694.23,4939 h60
  text "EXTERNAL" at 11426.46,4939 h60
  text "PER" at 9894.23,4821 h60
  text "IPC-D-275 CLASS 2 LEVEL C" at 10114.23,4821 h60
  text "MIL, HOLES" at 11602.46,4708.71 h60
  text "+/-" at 11210,4708 h60
  text "+/-" at 12064,4708 h60
  text "REGISTRATION TOLERANCES:" at 9694.23,4703 h60
  text "METAL" at 10894,4703 h60
  text "5" at 11470.2,4703 h60
  text "3" at 12303.2,4703 h60
  text "MIL" at 12419.46,4703 h60
  text "MATERIAL:" at 9619.46,4493.54 h60
  text "FR-4 High Tg" at 10605.9,4353.21 h60
  text "FR-408" at 10040.46,4344.64 h60
  text "X" at 10452.46,4344.64 h60
  text "OTHER" at 11528.46,4344.64 h60
  text "62 MIL (1.6mm) +/-10%" at 10360.56,4181.92 h60
  text "THICKNESS:" at 9694.23,4177.64 h60
  text "X" at 10232.4,4177.64 h60
  text "OTHER" at 11645.46,4177.64 h60
  text "TOLERANCE:" at 9694.23,4019.64 h60
  text "X" at 10533.53,4019.64 h60
  text "ANSI IPC-6012 TYPE 3 CLASS 2" at 10720.48,4019.64 h60
  text "OTHER +/-" at 10720.46,3863.64 h60
  text "BOW & TWIST:" at 9694.23,3706.64 h60
  text "X" at 10533.53,3706.64 h60
  text "ANSI IPC-6012 TYPE 3 CLASS 2" at 10720.48,3706.64 h60
  text "OTHER +/-" at 10720.46,3548.13 h60
  text "DRILLING:" at 9619.46,3409.64 h60
  text "REFERENCE:" at 9694.23,3292.64 h60
  text "X" at 10342.46,3292.64 h60
  text "AS SHOWN" at 10529.46,3292.64 h60
  text "X" at 11243.46,3292.64 h60
  text "NC_DRILL FILES" at 11380.46,3292.64 h60
  text "PTH MIN COPPER THICKNESS:" at 9694.23,3134.64 h60
  text "X" at 11044.46,3134.64 h60
  text "1MIL" at 11181.46,3134.64 h60
  text "OTHER" at 11678.46,3134.64 h60
  text "BOARD FINISH:" at 9619.46,2975.64 h60
  text "SILKSCREEN:" at 9774.68,2857.64 h60
  text "X" at 10723.46,2857.64 h60
  text "TOP" at 10849.46,2857.64 h60
  text "X" at 11233.46,2857.64 h60
  text "BOTTOM" at 11360.46,2857.64 h60
  text "SILKSCREEN COLOR:" at 9774.68,2690.64 h60
  text "X" at 10722.42,2690.64 h60
  text "WHITE" at 10849.46,2690.64 h60
  text "OTHER" at 11360.46,2690.64 h60
  text "SOLDER RESIST COLOR:" at 9774.68,2520.64 h60
  text "X" at 10342.42,2361.44 h60
  text "GREEN" at 10469.46,2361.44 h60
  text "BLUE" at 11060.46,2361.44 h60
  text "OTHER" at 11598.46,2361.44 h60
  text "IMMERSION GOLD (ENIG)" at 10680.46,2172.92 h60
  text "ENEPIG" at 12018,2169.64 h60
  text "SURFACE FINISH:" at 9619.46,2168.64 h60
  text "X" at 10493.51,2168.64 h60
  text "IMM. TIN/SILVER OR EQUIV" at 9949,2011.64 h60
  text "OTHER" at 11380.46,2011.64 h60
  text "X" at 10490,1835 h60
  text "ARRAY/PANEL:" at 9619.46,1832.64 h60
  text "CUT AND TRIM PER MECH LAYER 1" at 10680.46,1828.35 h60
  text "N.C. ROUTE" at 10680.46,1676.64 h60
  text "V. SCORE" at 11546.46,1676.64 h60
  text "CERTIFICATION:" at 9619.46,1539.64 h60
  text "MATERIALS AND WORKMANSHIP FOR ALL PCBS" at 10344.46,1539.64 h60
  text "TO MEET OR EXCEED THE REQUIREMENTS OF:" at 10344.46,1441.64 h60
  text "X" at 9970.96,1305.13 h60
  text "ANSI IPC-A-600F CLASS ->" at 10109.96,1305.13 h60
  text "X" at 11749.02,1305.13 h60
  text "2" at 11867.96,1305.14 h60
  text "1" at 11552.96,1303.64 h60
  text "3" at 12221.96,1303.64 h60
  text "X" at 9973.02,1145.64 h60
  text "UL 94V-0" at 10109.96,1145.64 h60
  text "X" at 10785.02,1145.64 h60
  text "RoHS" at 10921.96,1145.64 h60
  text "OTHER" at 11566.36,1145.64 h60
  text "PER ORDER" at 11963.42,1145.64 h60
  text "ADDITIONAL REQUIREMENTS:" at 9619.46,1004.64 h60
  text "MICROSECTION:" at 9694.23,889.64 h60
  text "YES" at 10599.96,889.64 h60
  text "REQUIRED" at 11461.46,733.49 h60
  text "BARE BOARD ELEC. TEST:" at 9694.23,730.64 h60
  text "NONE" at 10999.96,730.64 h60
  text "X" at 11334.46,730.64 h60
  text "PER ORDER" at 12053.46,730.64 h60
  text "MANUFACTURER'S UL:" at 9694.23,573.64 h60
  text "RAIL" at 10859.96,569.35 h60
  text "METAL" at 11351.77,569.35 h60
  text "X" at 11727,569 h60
  text "SILK" at 11863.46,569.35 h60
  text ".Layer_Name" at -1136,-1239.49 h60
M11 Gerber Information:
  lines w10: -2005,-1311.17 4595,-1311.17 ; -2005,-1107.83 4597,-1107.83 ; -2005,-904.5 -2005,-1514.5 2000,-1514.5 4597,-1514.5 4597,-904.5 -2004.5,-904.5 -2004.5,-1514.5 -429,-1514.5 ; 460,-1514.5 460,-904.5 ; 1727,-1107.83 1727,-904.5 ; 2567,-1107.83 2567,-904.5 ; 3189,-1521 3189,-1318.17
  text "ALL ARTWORK VIEWED FROM TOP SIDE" at -1941.5,-1036.67 h60
  text "BOARD #:" at 535,-1036.67 h60
  text ".PRJ_Number" at 1080.5,-1036.67 h60
  text "REV:" at 1925,-1036.67 h60
  text ".PCB_Rev" at 2216.5,-1036.67 h60
  text "SVN REV:" at 2763,-1036.67 h60
  text ".VersionControl_RevNumber" at 3269,-1036.67 h60
  text "LAYER NAME =" at -1941.5,-1239.49 h60
  text "PLOT NAME =" at -1941.5,-1445.34 h60
  text ".plot_File_Name" at -1136,-1445.34 h60
  text "GENERATED    :" at 537,-1445.34 h60
  text ".Print_Date" at 1406.5,-1445.34 h60
  text ".Print_Time" at 2135.5,-1445.34 h60
  text "TEXAS INSTRUMENTS" at 3400,-1445.34 h60
M12 Stackup:
  drawing of 295 lines, arcs and shapes, not listed
  text "Layer" at 7925,7245 h60
  text "Name" at 8334.91,7245 h60
  text "Material" at 9264.66,7245 h60
  text "Thickness" at 10124.42,7245 h60
  text "Constant" at 10774.26,7245 h60
  text "Board Layer Stack" at 11344.12,7245 h60
  text "1" at 7925,7125 h60
  text "Top Overlay" at 8334.91,7125 h60
  text "2" at 7925,7005 h60
  text "Top Solder" at 8334.91,7005 h60
  text "Solder Resist" at 9264.66,7005 h60
  text "0.40mil" at 10124.42,7005 h60
  text "3.5" at 10774.26,7005 h60
  text "3" at 7925,6885 h60
  text "Top Layer" at 8334.91,6885 h60
  text "Copper" at 9264.66,6885 h60
  text "2.80mil" at 10124.42,6885 h60
  text "4" at 7925,6765 h60
  text "Dielectric1" at 8334.91,6765 h60
  text "FR-4" at 9264.66,6765 h60
  text "10.00mil" at 10124.42,6765 h60
  text "4.8" at 10774.26,6765 h60
  text "5" at 7925,6645 h60
  text "MidLayer1" at 8334.91,6645 h60
  text "Copper" at 9264.66,6645 h60
  text "1.40mil" at 10124.42,6645 h60
  text "6" at 7925,6525 h60
  text "Dielectric2" at 8334.91,6525 h60
  text "FR-4" at 9264.66,6525 h60
  text "31.00mil" at 10124.42,6525 h60
  text "4.2" at 10774.26,6525 h60
  text "7" at 7925,6405 h60
  text "MidLayer2" at 8334.91,6405 h60
  text "Copper" at 9264.66,6405 h60
  text "1.40mil" at 10124.42,6405 h60
  text "8" at 7925,6285 h60
  text "Dielectric3" at 8334.91,6285 h60
  text "FR-4" at 9264.66,6285 h60
  text "10.00mil" at 10124.42,6285 h60
  text "4.2" at 10774.26,6285 h60
  text "9" at 7925,6165 h60
  text "Bottom Layer" at 8334.91,6165 h60
  text "Copper" at 9264.66,6165 h60
  text "2.80mil" at 10124.42,6165 h60
  text "10" at 7925,6045 h60
  text "Bottom Solder" at 8334.91,6045 h60
  text "Solder Resist" at 9264.66,6045 h60
  text "0.40mil" at 10124.42,6045 h60
  text "3.5" at 10774.26,6045 h60
  text "11" at 7925,5925 h60
  text "Bottom Overlay" at 8334.91,5925 h60
  text ".Layer_Name" at -1136,-1239.49 h60
M13 Component Bodies Top:
  text ".Layer_Name" at -1136,-1239.49 h60
M14 Component Bodies Bottom:
  text ".Layer_Name" at -1136,-1239.49 h60
M15 Courtyards Top:
  text ".Layer_Name" at -1136,-1239.49 h60
M16 Courtyards Bottom:
  text ".Layer_Name" at -1136,-1239.49 h60
Drill Drawing:
  text "Drill Table" at 3637,-391 h60
  text ".Layer_Name" at -1136,-1239.49 h60

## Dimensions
-1713,-791.5 to -713,-791.5 on M2 Board Dimensions
2648,2325 to 3178,1595 on M2 Board Dimensions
